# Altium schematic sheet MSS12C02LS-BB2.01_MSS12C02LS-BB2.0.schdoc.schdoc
size 127 x 99 mm
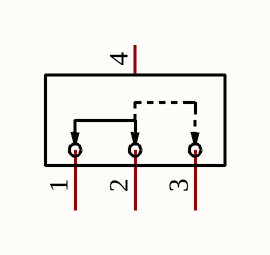
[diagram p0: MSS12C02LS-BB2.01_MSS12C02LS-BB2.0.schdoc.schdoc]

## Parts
U?  MSS12C02LS-BB2.0  [SW-SMD_MSS12C02LS-HB2.0-1]  (value not drawn)

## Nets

Not connected (* = marked no-connect by the designer): U? 1 2 3 4

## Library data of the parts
U? = MSS12C02LS-BB2.0: Manufacturer: SHOU HAN(首韩); Add into BOM: yes; Circuit: SPDT; Pin Style: SMDSplicing; Switch Length: 6.65mm; Switch Width: 2.75mm; Switch Height: 1.4mm; Current Rating (DC): 100mA; Voltage Rating (DC): 12V; Mechanical Life: 1万次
